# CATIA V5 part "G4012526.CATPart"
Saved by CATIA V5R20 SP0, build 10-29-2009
Part number: G4012526
Revision: 3
Definition: design
Nomenclature: G4012526
Source: made
Description: NOT SPECIFIED
Bounding box of the stored display mesh (mm): x 0 to 26, y -17.817 to 17.817, z -18 to 18
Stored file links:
  C:\Users\Raffaele\Desktop\3D X SITO CF\BOLEX\25-BUSH REF 401\G4012526.CATPart
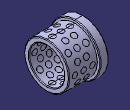
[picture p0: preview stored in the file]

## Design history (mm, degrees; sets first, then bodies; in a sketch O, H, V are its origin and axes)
Body1 "MANIFOLD_SOLID_BREP #5937" (main body)
  Solid1: solid without history
Body2 "MANIFOLD_SOLID_BREP #6084"
  Solid2: solid without history
Body3 "MANIFOLD_SOLID_BREP #6231"
  Solid3: solid without history
Body4 "MANIFOLD_SOLID_BREP #6378"
  Solid4: solid without history
Body5 "MANIFOLD_SOLID_BREP #6525"
  Solid5: solid without history
Body6 "MANIFOLD_SOLID_BREP #6674"
  Solid6: solid without history
Body7 "MANIFOLD_SOLID_BREP #6823"
  Solid7: solid without history
Body8 "MANIFOLD_SOLID_BREP #6972"
  Solid8: solid without history
Body9 "MANIFOLD_SOLID_BREP #7121"
  Solid9: solid without history
Body10 "MANIFOLD_SOLID_BREP #7270"
  Solid10: solid without history
Body11 "MANIFOLD_SOLID_BREP #7419"
  Solid11: solid without history
Body12 "MANIFOLD_SOLID_BREP #7568"
  Solid12: solid without history
Body13 "MANIFOLD_SOLID_BREP #7717"
  Solid13: solid without history
Body14 "MANIFOLD_SOLID_BREP #7866"
  Solid14: solid without history
Body15 "MANIFOLD_SOLID_BREP #8015"
  Solid15: solid without history
Body16 "MANIFOLD_SOLID_BREP #8164"
  Solid16: solid without history
Body17 "MANIFOLD_SOLID_BREP #8313"
  Solid17: solid without history
Body18 "MANIFOLD_SOLID_BREP #8462"
  Solid18: solid without history
Body19 "MANIFOLD_SOLID_BREP #8611"
  Solid19: solid without history
Body20 "MANIFOLD_SOLID_BREP #8761"
  Solid20: solid without history
Body21 "MANIFOLD_SOLID_BREP #8910"
  Solid21: solid without history
Body22 "MANIFOLD_SOLID_BREP #9059"
  Solid22: solid without history
Body23 "MANIFOLD_SOLID_BREP #9209"
  Solid23: solid without history
Body24 "MANIFOLD_SOLID_BREP #9358"
  Solid24: solid without history
Body25 "MANIFOLD_SOLID_BREP #9507"
  Solid25: solid without history
Body26 "MANIFOLD_SOLID_BREP #9656"
  Solid26: solid without history
Body27 "MANIFOLD_SOLID_BREP #9805"
  Solid27: solid without history
Body28 "MANIFOLD_SOLID_BREP #9954"
  Solid28: solid without history
Body29 "MANIFOLD_SOLID_BREP #10103"
  Solid29: solid without history
Body30 "MANIFOLD_SOLID_BREP #10252"
  Solid30: solid without history
Body31 "MANIFOLD_SOLID_BREP #10401"
  Solid31: solid without history
Body32 "MANIFOLD_SOLID_BREP #10548"
  Solid32: solid without history
Body33 "MANIFOLD_SOLID_BREP #10695"
  Solid33: solid without history
Body34 "MANIFOLD_SOLID_BREP #10844"
  Solid34: solid without history
Body35 "MANIFOLD_SOLID_BREP #10993"
  Solid35: solid without history
Body36 "MANIFOLD_SOLID_BREP #11143"
  Solid36: solid without history
Body37 "MANIFOLD_SOLID_BREP #11292"
  Solid37: solid without history
Body38 "MANIFOLD_SOLID_BREP #11441"
  Solid38: solid without history
Body39 "MANIFOLD_SOLID_BREP #11591"
  Solid39: solid without history
Body40 "MANIFOLD_SOLID_BREP #11740"
  Solid40: solid without history
Body41 "MANIFOLD_SOLID_BREP #11889"
  Solid41: solid without history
